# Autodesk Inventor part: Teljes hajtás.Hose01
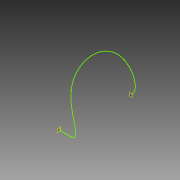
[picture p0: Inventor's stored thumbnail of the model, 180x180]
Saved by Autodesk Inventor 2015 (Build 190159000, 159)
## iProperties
StyleName: _Piping Style 20
ActiveState: True
Angle: UnInitValue
BendRadius: 0.500 in
CouplingKey: UnInitValue
DefaultBendRadius: UnInitValue
Diameter: 1/4
DiameterType: Nominal
Elbow45Key: UnInitValue
Elbow90Key: UnInitValue
ElbowCustomKey: UnInitValue
Ending: UnInitValue
FittingMaterial: UnInitValue
FittingStandard: UnInitValue
FlangeKey: UnInitValue
Gap: UnInitValue
GasketKey: UnInitValue
ID: 0,635
IsButtWelded: UnInitValue
IsFlanged: UnInitValue
IsSelfDraining: UnInitValue
Material: UnInitValue
MixedUnits: UnInitValue
Name: Hydraulic Hose - No Fittings
OD: 1,4986
PipeKey: v3#d489867e-ac9b-47ea-b952-0a1b885f66be#1
PipeType: Flexible Hose
PipingComponentColor: Blue - Wall Paint - Glossy
RoundUpValue: 0.125 in
RouteDirection45: UnInitValue
RouteDirection90: UnInitValue
Schedule: ID=0.25
ShowGap: UnInitValue
Standard: UnInitValue
SuppressEndFitting: True
SuppressStartFitting: True
UseFlangsForCouplings: UnInitValue
UseSubASM: True
_ComponentInfo: <CS><C N="Pipe" R="0,749300" OR="0,749300" IR="0,317500" PL="PL" PartType="pipe" SymKey="" PN="Parker hidraulikatömlő - No Skive 1/4"><CO N="1"><FE V="0"/><FD V
Created: 2013-02
Part Number: Teljes hajtás.Hose01
Material: Generic
Document SubType Name: Modeling
Designer: Marci
Density: 1 g/cm^3
Appearance: Default
_PSKETCH_SNAP: False
_PSKETCH_RSNP: False
_BASENETWORK_NOTAUTODIMENSION: False
Author: Marci
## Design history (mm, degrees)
workpoint "Work Point1"
workplane "Work Plane1"
workpoint "Work Point2"
workplane "Work Plane2"
sketch "3D Sketch1" dims "d0" = 10, "d1" = 0.1 (derived), "d2" = 10, "d3" = 0.1 (derived)
other parameters: "B" = 12.7 [user parameter]
